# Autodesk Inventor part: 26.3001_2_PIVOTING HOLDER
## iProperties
Created: 2009-09
Part Number: 26.3001_2_PIVOTING HOLDER
Material: Steel
Document SubType Name: Modeling
Designer: Administrator
Mass: 284.618 g
Surface Area: 270.733 cm^2
Volume: 36.2571 cm^3
Density: 7.85 g/cm^3
Author: Administrator
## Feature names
1. Base1
